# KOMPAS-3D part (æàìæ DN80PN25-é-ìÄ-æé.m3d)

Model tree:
1. Объединить компоненты:1  (labels: СЕНС DN80PN25-В-НО)
2. Эскиз:1
3. Операция выдавливания:1
     Расстояние 1 = 14
4. Фаска:1
     Угол = 45; Длина 1 = 2; Длина 2 = 2

Referenced files in D:\Савин\!СЕНСОР\3D для заказчика\!Новый перечень\СЕНС\6. СЕНС-В-НО\DN80\: СЕНС DN80PN25-В-НО.a3d
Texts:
  СЕНС DN80PN25-В-НО-СВ
  ООО НПП Сенсор
  СЕНС DN80PN25-В-НО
